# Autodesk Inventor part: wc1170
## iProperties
Shininess: 64.0
Length Units: 11272
Angle Units: 11279
Time Units: 11290
Mass Units: 11286
Length Display Precision: 3
Angle Display Precision: 2
Compacted: True
Part Number: wc1170
Document SubType Name: Modeling
Created: 2004-08
Designer: John Blackburn
Manufacturer: Standard
Standards Organization: Custom
Material: Phenolic
Density: 0.0
Volumn: 0.0
Area: 0.0
PropertySet Name: Model Information
Control State: 0
Master: False
Checked Out: False
Author: John Blackburn
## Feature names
1. Base1
